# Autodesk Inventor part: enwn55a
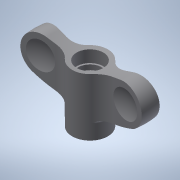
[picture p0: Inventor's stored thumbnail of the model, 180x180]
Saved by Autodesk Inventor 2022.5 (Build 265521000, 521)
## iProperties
Created: 2016-12
Part Number: enwn55a
Material: 一般
Document SubType Name: Modeling
Designer: imaocorp
Density: 1 g/cm^3
Appearance: 既定
Author: imaocorp
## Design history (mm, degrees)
node "enwn55a.x_t1"
node "enwn55a"
node "Base1"
